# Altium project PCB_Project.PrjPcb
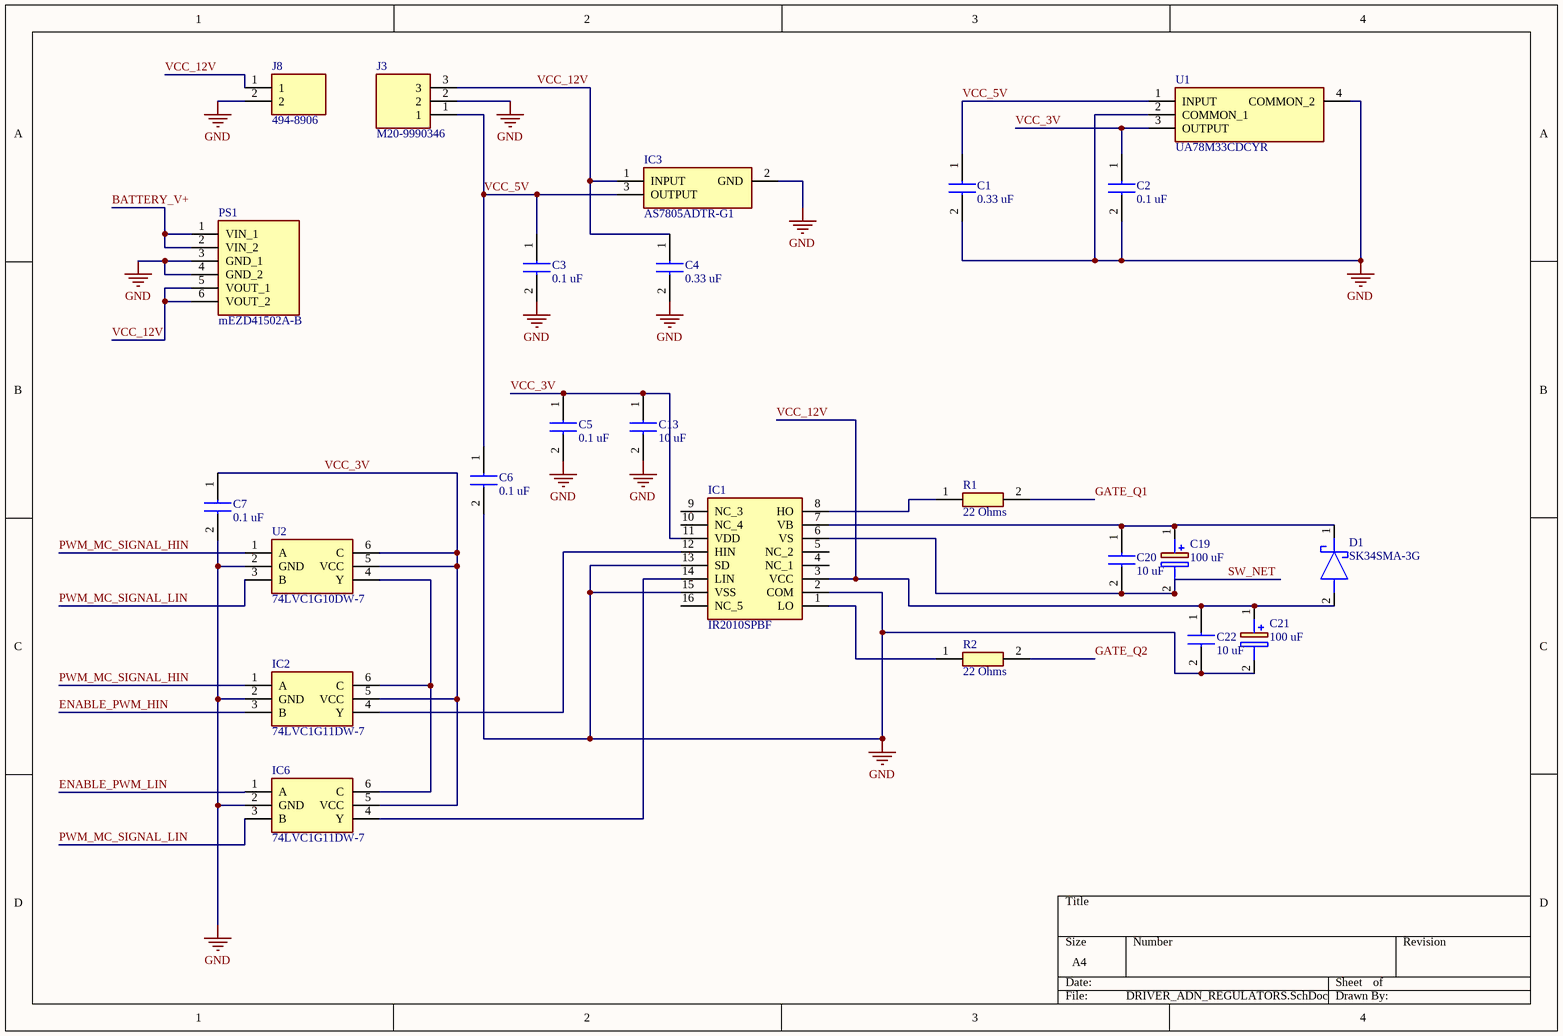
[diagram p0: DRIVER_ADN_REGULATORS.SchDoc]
5 sheets, 99 parts. Net scope: global (net labels, ports and power ports of the same name join across sheets).
Board file: PCB1.PcbDoc
Sheets:
  DRIVER_ADN_REGULATORS.SchDoc
  MOSFET_AND_INTRUMENTAL_AMPLIFIERS.SchDoc
  MCU.SchDoc
  CURRENT_SENSE.SchDoc
  DRIVER_2.SchDoc

## Sheet DRIVER_ADN_REGULATORS.SchDoc
size A4; SheetNumber: 1; SheetTotal: 4

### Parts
C1  0.33 uF  [C0805]
C2  0.1 uF  [C0805]
C3  0.1 uF  [C0805]
C4  0.33 uF  [C0805]
C5  0.1 uF  [C0805]
C6  0.1 uF  [C0805]
C7  0.1 uF  [C0805]
C13  10 uF  [CAPC3216X180N]
C19  100 uF  [CAPPRD250W52D630H1250]
C20  10 uF  [CAPC3216X180N]
C21  100 uF  [CAPPRD250W52D630H1250]
C22  10 uF  [CAPC3216X180N]
D1  SK34SMA-3G  [DIOM5027X240N]
IC1  IR2010SPBF  [SOIC127P1032X265-16N]
IC2  74LVC1G11DW-7  [SOT65P210X110-6N]
IC3  AS7805ADTR-G1  [AS7805ADTRG1]
IC6  74LVC1G11DW-7  [SOT65P210X110-6N]
J3  M20-9990346  [HDRV3W64P0X254_1X3_762X254X864P]
J8  494-8906  [SHDR2W100P0X500_1X2_1000X750X1000P]
PS1  mEZD41502A-B  [mEZD41502AB]
R1  22 Ohms  [RESC6331X75N]
R2  22 Ohms  [RESC6331X75N]
U1  UA78M33CDCYR  [SOT230P700X180-4N]
U2  74LVC1G10DW-7  [SOT65P210X110-6N]

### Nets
GND: C1.2 C2.2 C3.2 C4.2 C5.2 C6.2 C7.2 C13.2 C21.2(-) C22.2 IC1.2(COM) IC1.13(SD) IC1.15(VSS) IC2.2(GND) IC3.2(GND) IC6.2(GND) J3.2 J8.2 PS1.3(GND_1) PS1.4(GND_2) U1.2(COMMON_1) U1.4(COMMON_2) U2.2(GND)
BATTERY_V+: PS1.1(VIN_1) PS1.2(VIN_2)
ENABLE_PWM_HIN: IC2.3(B)
ENABLE_PWM_LIN: IC6.1(A)
GATE_Q1: R1.2
GATE_Q2: R2.2
PWM_MC_SIGNAL_HIN: IC2.1(A) U2.1(A)
PWM_MC_SIGNAL_LIN: IC6.3(B) U2.3(B)
SW_NET: C19.2(-) C20.2 IC1.6(VS)
VCC_3V: C2.1 C5.1 C7.1 C13.1 IC1.11(VDD) IC2.5(VCC) IC6.5(VCC) U1.3(OUTPUT) U2.5(VCC) U2.6(C)
VCC_5V: C1.1 C3.1 C6.1 IC3.3(OUTPUT) J3.1 U1.1(INPUT)
VCC_12V: C4.1 C21.1(+) C22.1 D1.2(A) IC1.3(VCC) IC3.1(INPUT) J3.3 J8.1 PS1.5(VOUT_1) PS1.6(VOUT_2)
NetC19_1: C19.1(+) C20.1 D1.1(K) IC1.7(VB)
NetIC1_1: IC1.1(LO) R2.1
NetIC1_8: IC1.8(HO) R1.1
NetIC1_12: IC1.12(HIN) IC2.4(Y)
NetIC1_14: IC1.14(LIN) IC6.4(Y)
NetIC2_6: IC2.6(C) IC6.6(C) U2.4(Y)

Not connected (* = marked no-connect by the designer): IC1 4(NC_1) 5(NC_2) 9(NC_3) 10(NC_4) 16(NC_5)

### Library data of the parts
C1 C4 = C0805C334K5RACAUTO: Capacitor; Manufacturer_Name: KEMET
C2 C3 C5-C7 = C0805C104M5RACTU: Capacitor; Manufacturer_Name: KEMET
C13 C20 C22 = CL31B106KAHNNNE: Capacitor; Manufacturer_Name: SAMSUNG
C19 C21 = 860010473007: Capacitor Polarised; Manufacturer_Name: Wurth Elektronik
D1 = SK34SMA-3G: Schottky Diode; Manufacturer_Name: Diotec
IC1 = IR2010SPBF: Integrated Circuit; Manufacturer_Name: Infineon
IC2 IC6 = 74LVC1G11DW-7: Integrated Circuit; Manufacturer_Name: Diodes Incorporated
IC3 = AS7805ADTR-G1: Integrated Circuit; Manufacturer_Name: Diodes Incorporated
J3 = M20-9990346: Connector; Manufacturer_Name: Harwin
J8 = 494-8906: Connector; Manufacturer_Name: RS Pro
PS1 = mEZD41502A-B: Power Supply; Manufacturer_Name: Monolithic Power Systems (MPS)
R1 R2 = CR2512-JW-220ELF: Resistor; Manufacturer_Name: Bourns
U1 = UA78M33CDCYR: Undefined or Miscellaneous; Manufacturer_Name: Texas Instruments
U2 = 74LVC1G10DW-7: Undefined or Miscellaneous; Manufacturer_Name: Diodes Incorporated

## Sheet MOSFET_AND_INTRUMENTAL_AMPLIFIERS.SchDoc
size A4; SheetNumber: 2; SheetTotal: 5
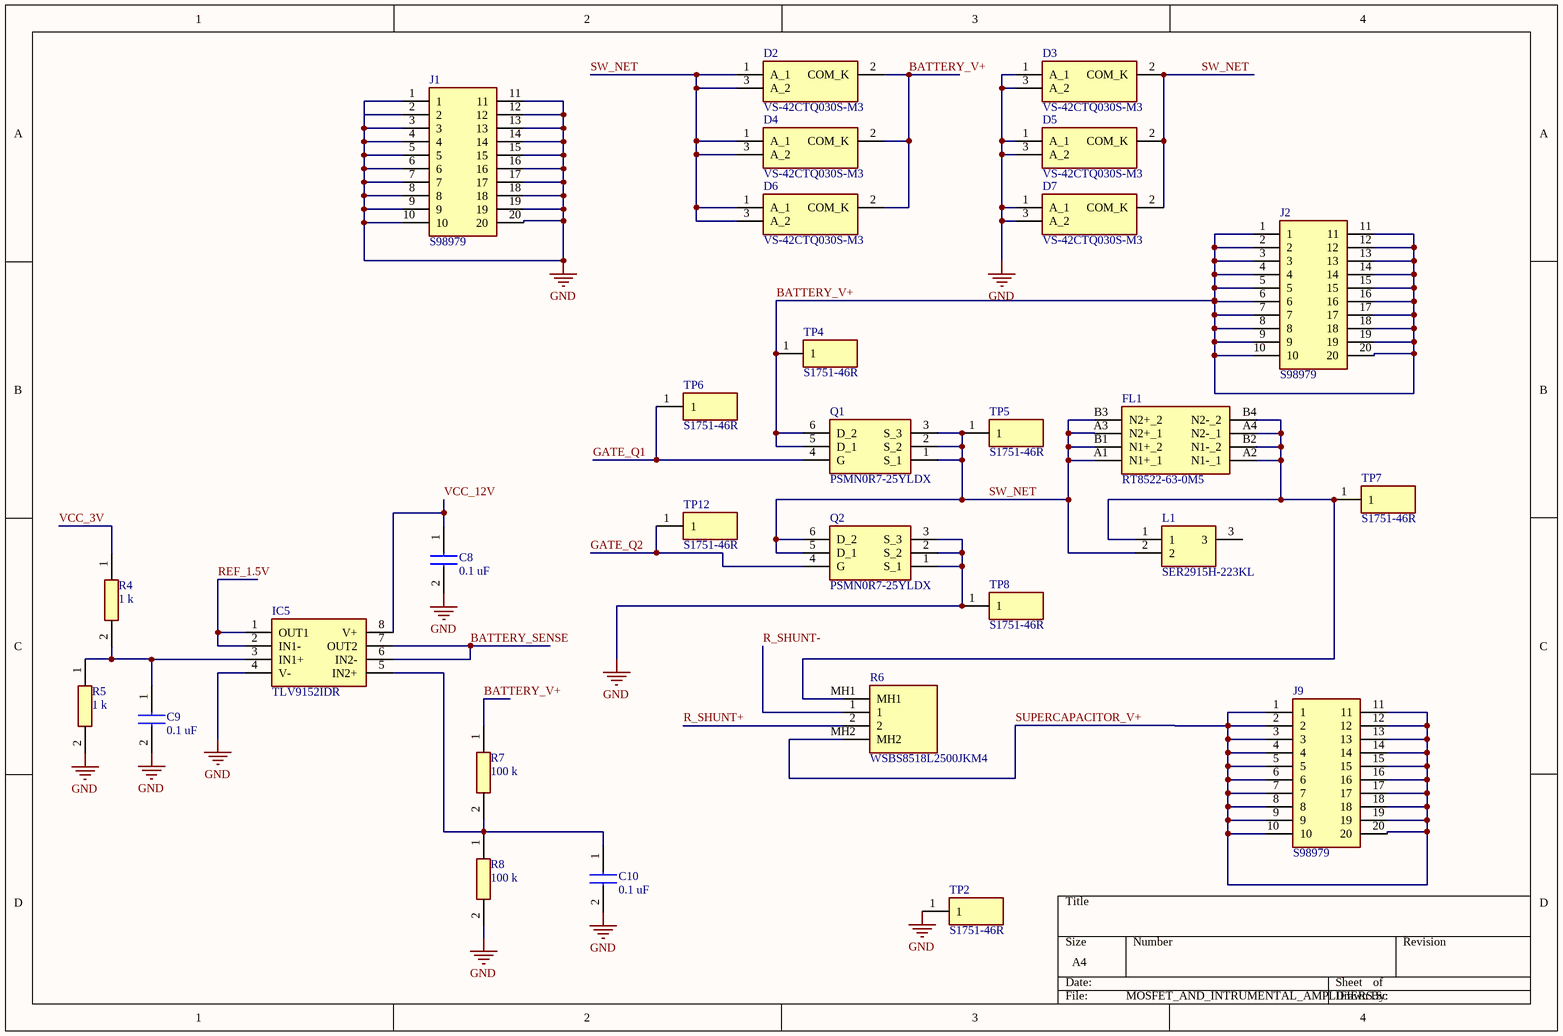
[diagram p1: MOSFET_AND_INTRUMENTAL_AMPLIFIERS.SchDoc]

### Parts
C8  0.1 uF  [C0805]
C9  0.1 uF  [C0805]
C10  0.1 uF  [C0805]
D2  VS-42CTQ030S-M3  [VS42CTQ030SM3]
D3  VS-42CTQ030S-M3  [VS42CTQ030SM3]
D4  VS-42CTQ030S-M3  [VS42CTQ030SM3]
D5  VS-42CTQ030S-M3  [VS42CTQ030SM3]
D6  VS-42CTQ030S-M3  [VS42CTQ030SM3]
D7  VS-42CTQ030S-M3  [VS42CTQ030SM3]
FL1  RT8522-63-0M5  [RT8522630M5]
IC5  TLV9152IDR  [SOIC127P600X175-8N]
J1  S98979  [S98979]
J2  S98979  [S98979]
J9  S98979  [S98979]
L1  SER2915H-223KL  [SER2915H223KL]
Q1  PSMN0R7-25YLDX  [BUK7J1R440HX]
Q2  PSMN0R7-25YLDX  [BUK7J1R440HX]
R4  1 k  [RESC2012X50N]
R5  1 k  [RESC2012X50N]
R6  WSBS8518L2500JKM4  [WSBS8518L2500JKM4]
R7  100 k  [RESC2012X60N]
R8  100 k  [RESC2012X60N]
TP2  S1751-46R  [S175146R]
TP4  S1751-46R  [S175146R]
TP5  S1751-46R  [S175146R]
TP6  S1751-46R  [S175146R]
TP7  S1751-46R  [S175146R]
TP8  S1751-46R  [S175146R]
TP12  S1751-46R  [S175146R]

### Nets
GND: C8.2 C9.2 C10.2 D3.1(A_1) D3.3(A_2) D5.1(A_1) D5.3(A_2) D7.1(A_1) D7.3(A_2) IC5.4(V-) J1.1 J1.2 J1.3 J1.4 J1.5 J1.6 J1.7 J1.8 J1.9 J1.10 J1.11 J1.12 J1.13 J1.14 J1.15 J1.16 J1.17 J1.18 J1.19 J1.20 Q2.1(S_1) Q2.2(S_2) Q2.3(S_3) R5.2 R8.2 TP2.1 TP8.1
BATTERY_SENSE: IC5.6(IN2-) IC5.7(OUT2)
BATTERY_V+: D2.2(COM_K) D4.2(COM_K) D6.2(COM_K) J2.1 J2.2 J2.3 J2.4 J2.5 J2.6 J2.7 J2.8 J2.9 J2.10 J2.11 J2.12 J2.13 J2.14 J2.15 J2.16 J2.17 J2.18 J2.19 J2.20 Q1.5(D_1) Q1.6(D_2) R7.1 TP4.1
GATE_Q1: Q1.4(G) TP6.1
GATE_Q2: Q2.4(G) TP12.1
R_SHUNT+: R6.2
R_SHUNT-: R6.1
REF_1.5V: IC5.1(OUT1) IC5.2(IN1-)
SUPERCAPACITOR_V+: J9.1 J9.2 J9.3 J9.4 J9.5 J9.6 J9.7 J9.8 J9.9 J9.10 J9.11 J9.12 J9.13 J9.14 J9.15 J9.16 J9.17 J9.18 J9.19 J9.20 R6.MH2
SW_NET: D2.1(A_1) D2.3(A_2) D3.2(COM_K) D4.1(A_1) D4.3(A_2) D5.2(COM_K) D6.1(A_1) D6.3(A_2) D7.2(COM_K) FL1.A1(N1+_1) FL1.A3(N2+_1) FL1.B1(N1+_2) FL1.B3(N2+_2) L1.2 Q1.1(S_1) Q1.2(S_2) Q1.3(S_3) Q2.5(D_1) Q2.6(D_2) TP5.1
VCC_3V: R4.1
VCC_12V: C8.1 IC5.8(V+)
NetC9_1: C9.1 IC5.3(IN1+) R4.2 R5.1
NetC10_1: C10.1 IC5.5(IN2+) R7.2 R8.1
NetFL1_A2: FL1.A2(N1-_1) FL1.A4(N2-_1) FL1.B2(N1-_2) FL1.B4(N2-_2) L1.1 R6.MH1 TP7.1

Not connected (* = marked no-connect by the designer): L1 3

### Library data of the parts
C8-C10 = C0805C104M5RACTU: Capacitor; Manufacturer_Name: KEMET
D2-D7 = VS-42CTQ030S-M3: Schottky Diode; Manufacturer_Name: Vishay
FL1 = RT8522-63-0M5: Filter; Manufacturer_Name: Schaffner
IC5 = TLV9152IDR: Integrated Circuit; Manufacturer_Name: Texas Instruments
J1 J2 J9 = S98979: Connector; Manufacturer_Name: Wurth Elektronik
L1 = SER2915H-223KL: Inductor; Manufacturer_Name: COILCRAFT
Q1 Q2 = PSMN0R7-25YLDX: MOSFET (N-Channel); Manufacturer_Name: Nexperia
R4 R5 = CRCW08051K00FKEA: Resistor; Manufacturer_Name: Vishay
R6 = WSBS8518L2500JKM4: Resistor; Manufacturer_Name: Vishay
R7 R8 = CR0805-FX-1003ELF: Resistor; Manufacturer_Name: Bourns
TP2 TP4-TP8 TP12 = S1751-46R: Test Point; Manufacturer_Name: Harwin

## Sheet MCU.SchDoc
size A4; SheetNumber: 3; SheetTotal: 5
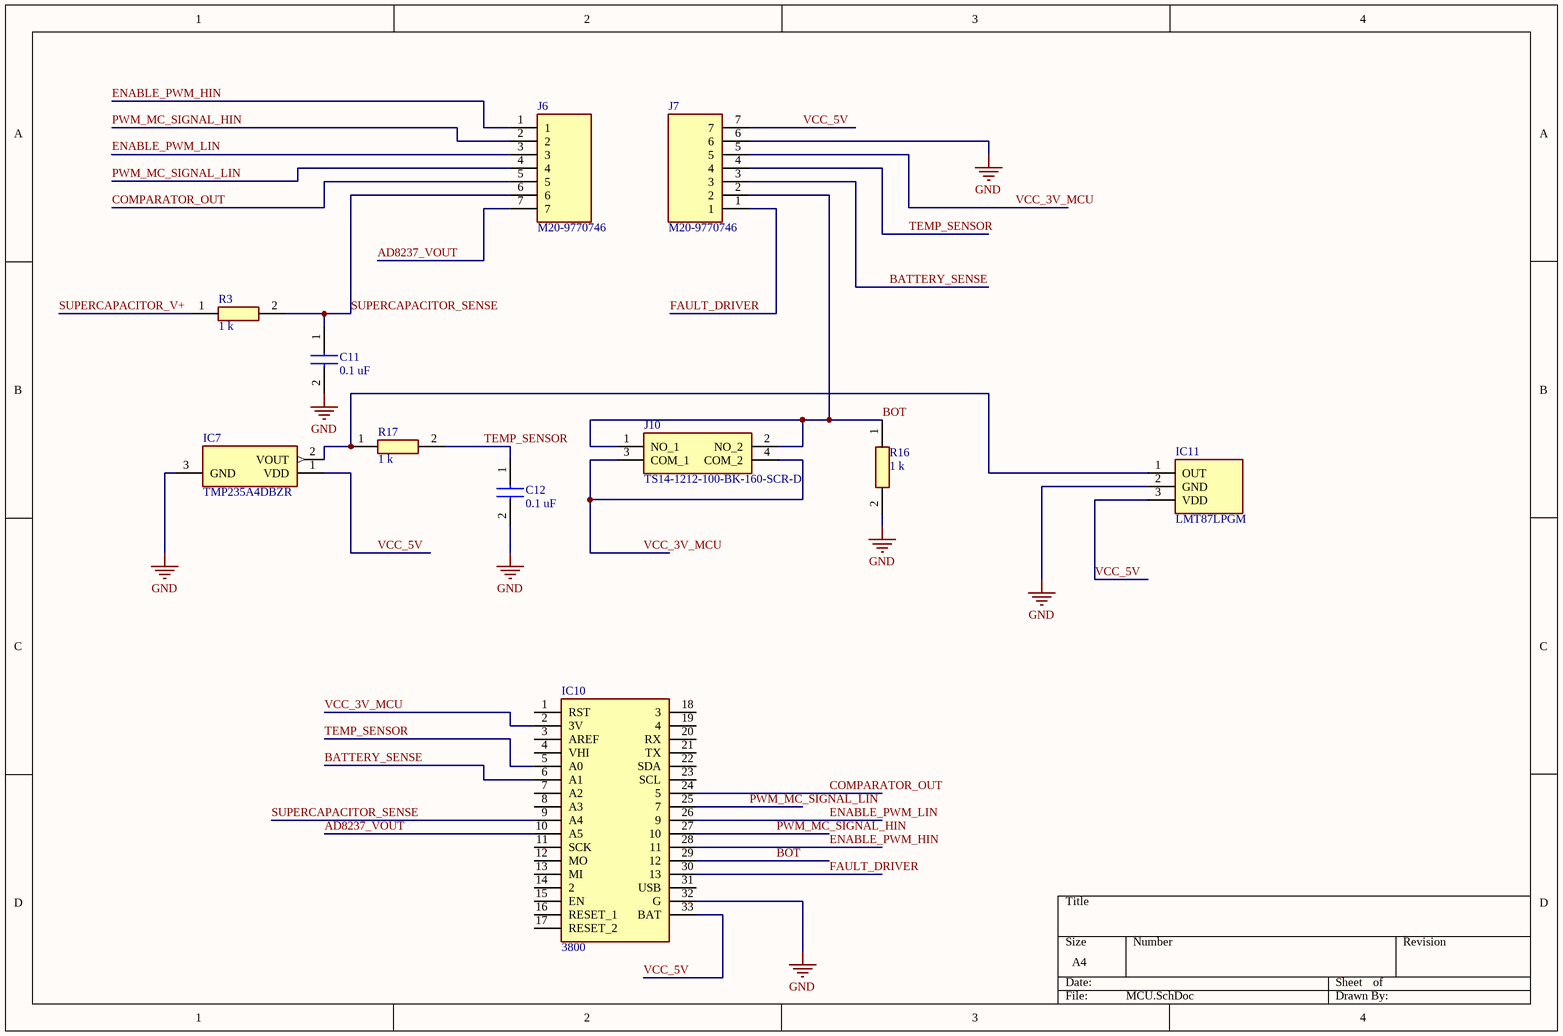
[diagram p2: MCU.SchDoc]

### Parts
C11  0.1 uF  [C0805]
C12  0.1 uF  [C0805]
IC7  TMP235A4DBZR  [SOT95P237X112-3N]
IC10  3800  [3800]
IC11  LMT87LPGM  [TO127P162X315X490-3P]
J6  M20-9770746  [HDRV7W66P0X254_1X7_1778X254X844P]
J7  M20-9770746  [HDRV7W66P0X254_1X7_1778X254X844P]
J10  TS14-1212-100-BK-160-SCR-D  [TS141212100BK160SCRD]
R3  1 k  [RESC2012X50N]
R16  1 k  [RESC2012X50N]
R17  1 k  [RESC2012X50N]

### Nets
GND: C11.2 C12.2 IC7.3(GND) IC10.32(G) IC11.2(GND) J7.6 R16.2
AD8237_VOUT: IC10.10(A5) J6.7
BATTERY_SENSE: IC10.6(A1) J7.3
BOT: IC10.29(12) J7.2 J10.1(NO_1) J10.2(NO_2) R16.1
COMPARATOR_OUT: IC10.24(5) J6.5
ENABLE_PWM_HIN: IC10.28(11) J6.1
ENABLE_PWM_LIN: IC10.26(9) J6.3
FAULT_DRIVER: IC10.30(13) J7.1
PWM_MC_SIGNAL_HIN: IC10.27(10) J6.2
PWM_MC_SIGNAL_LIN: IC10.25(7) J6.4
SUPERCAPACITOR_SENSE: C11.1 IC10.9(A4) J6.6 R3.2
SUPERCAPACITOR_V+: R3.1
TEMP_SENSOR: C12.1 IC10.5(A0) J7.4 R17.2
VCC_3V_MCU: IC10.2(3V) J7.5 J10.3(COM_1) J10.4(COM_2)
VCC_5V: IC7.1(VDD) IC10.33(BAT) IC11.3(VDD) J7.7
NetIC7_2: IC7.2(VOUT) IC11.1(OUT) R17.1

Not connected (* = marked no-connect by the designer): IC10 1(RST) 3(AREF) 4(VHI) 7(A2) 8(A3) 11(SCK) 12(MO) 13(MI) 14(2) 15(EN) 16(RESET_1) 17(RESET_2) 18(3) 19(4) 20(RX) 21(TX) 22(SDA) 23(SCL) 31(USB)

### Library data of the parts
C11 C12 = C0805C104M5RACTU: Capacitor; Manufacturer_Name: KEMET
IC7 = TMP235A4DBZR: Integrated Circuit; Manufacturer_Name: Texas Instruments
IC10 = 3800: Integrated Circuit; Manufacturer_Name: Adafruit
IC11 = LMT87LPGM: Integrated Circuit; Manufacturer_Name: Texas Instruments
J6 J7 = M20-9770746: Connector; Manufacturer_Name: Harwin
J10 = TS14-1212-100-BK-160-SCR-D: Connector; Manufacturer_Name: Same Sky
R3 R16 R17 = CRCW08051K00FKEA: Resistor; Manufacturer_Name: Vishay

## Sheet CURRENT_SENSE.SchDoc
size A4; SheetNumber: 4; SheetTotal: 4
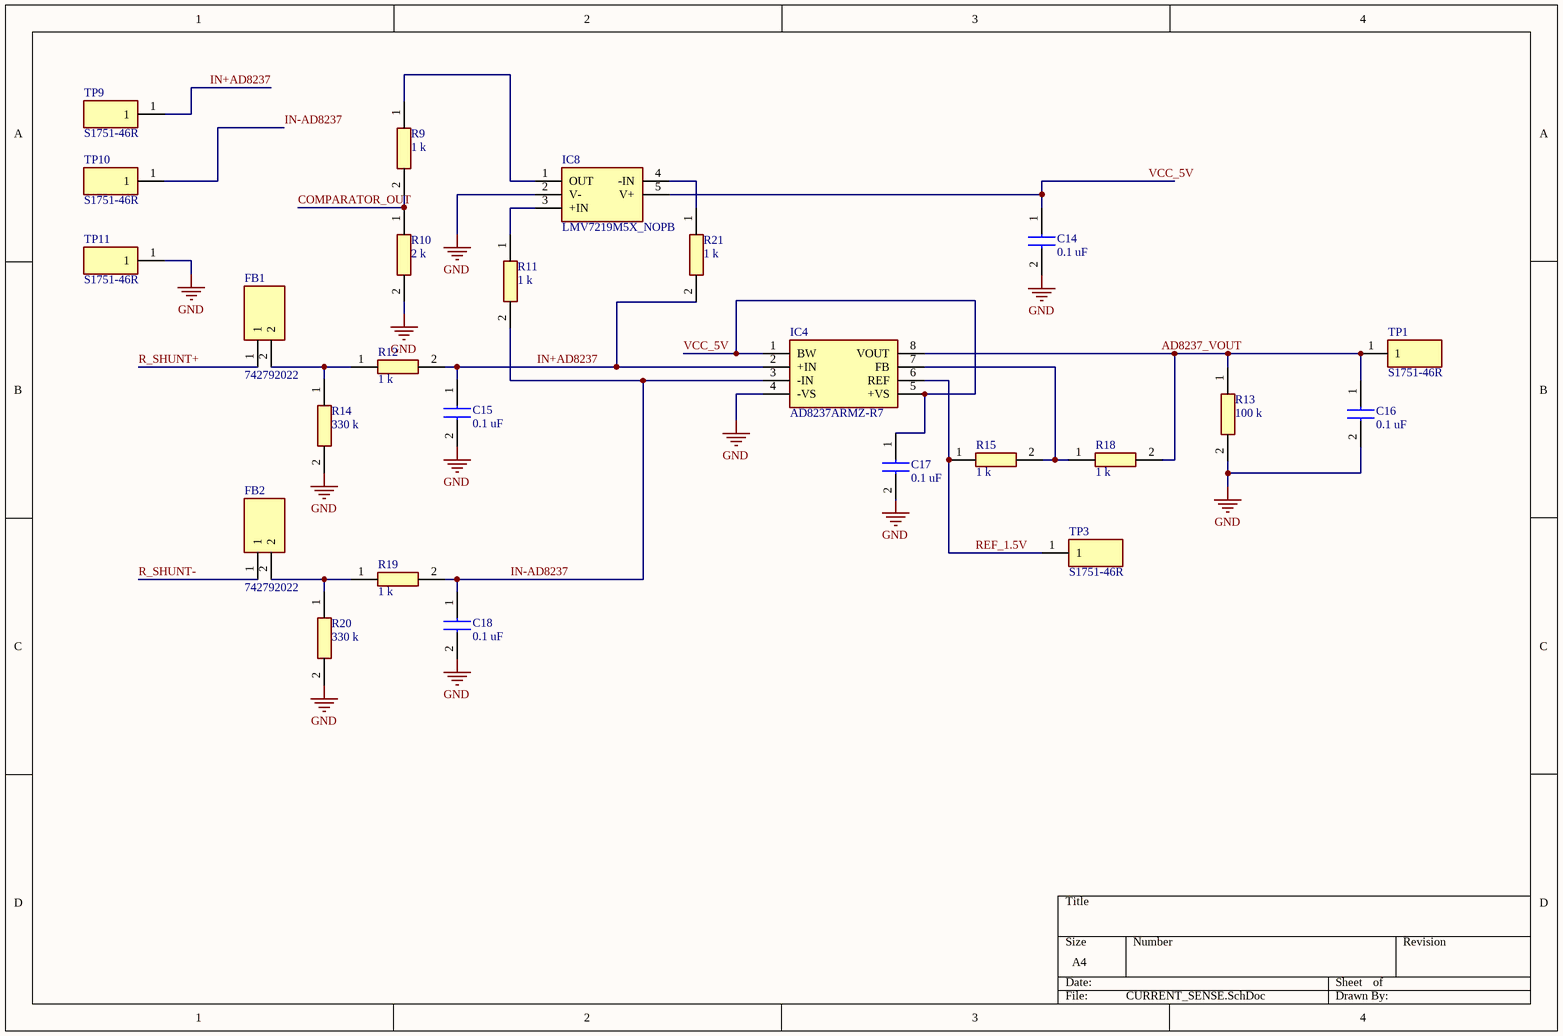
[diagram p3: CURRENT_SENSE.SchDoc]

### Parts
C14  0.1 uF  [C0805]
C15  0.1 uF  [C0805]
C16  0.1 uF  [C0805]
C17  0.1 uF  [C0805]
C18  0.1 uF  [C0805]
FB1  742792022  [BEADC2012X110N]
FB2  742792022  [BEADC2012X110N]
IC4  AD8237ARMZ-R7  [SOP65P490X110-8N]
IC8  LMV7219M5X_NOPB  [SOT95P280X145-5N]
R9  1 k  [RESC2012X50N]
R10  2 k  [RESC2012X60N]
R11  1 k  [RESC2012X50N]
R12  1 k  [RESC2012X50N]
R13  100 k  [RESC2012X60N]
R14  330 k  [RESC2012X70N]
R15  1 k  [RESC2012X50N]
R18  1 k  [RESC2012X50N]
R19  1 k  [RESC2012X50N]
R20  330 k  [RESC2012X70N]
R21  1 k  [RESC2012X50N]
TP1  S1751-46R  [S175146R]
TP3  S1751-46R  [S175146R]
TP9  S1751-46R  [S175146R]
TP10  S1751-46R  [S175146R]
TP11  S1751-46R  [S175146R]

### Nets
GND: C14.2 C15.2 C16.2 C17.2 C18.2 IC4.4(-VS) IC8.2(V-) R10.2 R13.2 R14.2 R20.2 TP11.1
AD8237_VOUT: C16.1 IC4.8(VOUT) R13.1 R18.2 TP1.1
COMPARATOR_OUT: R9.2 R10.1
IN+AD8237: C15.1 IC4.2(+IN) R12.2 R21.2 TP9.1
IN-AD8237: C18.1 IC4.3(-IN) R11.2 R19.2 TP10.1
R_SHUNT+: FB1.1
R_SHUNT-: FB2.1
REF_1.5V: IC4.6(REF) R15.1 TP3.1
VCC_5V: C14.1 C17.1 IC4.1(BW) IC4.5(+VS) IC8.5(V+)
NetFB1_2: FB1.2 R12.1 R14.1
NetFB2_2: FB2.2 R19.1 R20.1
NetIC4_7: IC4.7(FB) R15.2 R18.1
NetIC8_1: IC8.1(OUT) R9.1
NetIC8_3: IC8.3(+IN) R11.1
NetIC8_4: IC8.4(-IN) R21.1

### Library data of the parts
C14-C18 = C0805C104M5RACTU: Capacitor; Manufacturer_Name: KEMET
FB1 FB2 = 742792022: Ferrite Bead; Manufacturer_Name: Wurth Elektronik
IC4 = AD8237ARMZ-R7: Integrated Circuit; Manufacturer_Name: Analog Devices
IC8 = LMV7219M5X_NOPB: Integrated Circuit; Manufacturer_Name: Texas Instruments; Manufacturer_Part_Number: LMV7219M5X/NOPB
R9 R11 R12 R15 R18 R19 R21 = CRCW08051K00FKEA: Resistor; Manufacturer_Name: Vishay
R10 = CR0805-JW-202ELF: Resistor; Manufacturer_Name: Bourns
R13 = CR0805-FX-1003ELF: Resistor; Manufacturer_Name: Bourns
R14 R20 = ERJ-6GEYJ334V: Resistor; Manufacturer_Name: Panasonic
TP1 TP3 TP9-TP11 = S1751-46R: Test Point; Manufacturer_Name: Harwin

## Sheet DRIVER_2.SchDoc
size A4; SheetNumber: 5; SheetTotal: 5
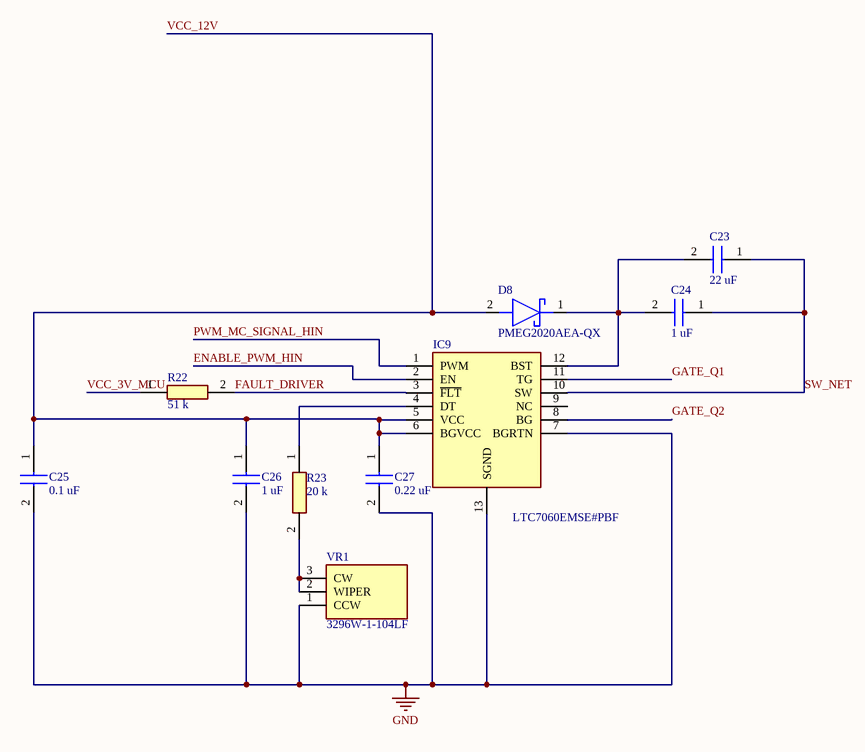
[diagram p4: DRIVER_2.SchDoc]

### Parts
C23  22 uF  [CAPC3225X270N]
C24  1 uF  [CAPC2012X135N]
C25  0.1 uF  [CAPC2012X88N]
C26  1 uF  [CAPC2012X135N]
C27  0.22 uF  [CAPC2012X140N]
D8  PMEG2020AEA-QX  [SOD2512X110N]
IC9  LTC7060EMSE#PBF  [SOP65P490X110-13N]
R22  51 k  [RESC2013X65N]
R23  20 k  [RESC2012X60N]
VR1  3296W-1-104LF  [3296W1503LF]

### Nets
GND: C25.2 C26.2 C27.2 IC9.7(BGRTN) IC9.13(SGND) VR1.1(CCW)
ENABLE_PWM_HIN: IC9.2(EN)
FAULT_DRIVER: IC9.3(~{FLT}) R22.2
GATE_Q1: IC9.11(TG)
GATE_Q2: IC9.8(BG)
PWM_MC_SIGNAL_HIN: IC9.1(PWM)
SW_NET: C23.1 C24.1 IC9.10(SW)
VCC_3V_MCU: R22.1
VCC_12V: C25.1 C26.1 C27.1 D8.2(A) IC9.5(VCC) IC9.6(BGVCC)
NetC23_2: C23.2 C24.2 D8.1(K) IC9.12(BST)
NetIC9_4: IC9.4(DT) R23.1
NetR23_2: R23.2 VR1.2(WIPER) VR1.3(CW)

Not connected (* = marked no-connect by the designer): IC9 9(NC)

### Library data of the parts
C23 = CL32B226KAJNNNE: Capacitor; Manufacturer_Name: SAMSUNG
C24 C26 = CL21B105MBFNNNE: Capacitor; Manufacturer_Name: SAMSUNG
C25 = C0805C104M5RAC: Capacitor; Manufacturer_Name: KEMET
C27 = C0805C224K5RAC7800: Capacitor; Manufacturer_Name: KEMET
D8 = PMEG2020AEA-QX: Schottky Diode; Manufacturer_Name: Nexperia
IC9 = LTC7060EMSE#PBF: Integrated Circuit; Manufacturer_Name: Analog Devices
R22 = 0805W8F5102T5E: Resistor; Manufacturer_Name: UNI-ROYAL(Uniroyal Elec)
R23 = CR0805-FX-2002ELF: Resistor; Manufacturer_Name: Bourns
VR1 = 3296W-1-104LF: Variable Resistor; Manufacturer_Name: Bourns

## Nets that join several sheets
GND: DRIVER_ADN_REGULATORS (23 pins), MOSFET_AND_INTRUMENTAL_AMPLIFIERS (37 pins), MCU (7 pins), CURRENT_SENSE (12 pins), DRIVER_2 (6 pins)
AD8237_VOUT: MCU (IC10.10 J6.7), CURRENT_SENSE (5 pins)
BATTERY_SENSE: MOSFET_AND_INTRUMENTAL_AMPLIFIERS (IC5.6 IC5.7), MCU (IC10.6 J7.3)
BATTERY_V+: DRIVER_ADN_REGULATORS (PS1.1 PS1.2), MOSFET_AND_INTRUMENTAL_AMPLIFIERS (27 pins)
COMPARATOR_OUT: MCU (IC10.24 J6.5), CURRENT_SENSE (R9.2 R10.1)
ENABLE_PWM_HIN: DRIVER_ADN_REGULATORS (IC2.3), MCU (IC10.28 J6.1), DRIVER_2 (IC9.2)
ENABLE_PWM_LIN: DRIVER_ADN_REGULATORS (IC6.1), MCU (IC10.26 J6.3)
FAULT_DRIVER: MCU (IC10.30 J7.1), DRIVER_2 (IC9.3 R22.2)
GATE_Q1: DRIVER_ADN_REGULATORS (R1.2), MOSFET_AND_INTRUMENTAL_AMPLIFIERS (Q1.4 TP6.1), DRIVER_2 (IC9.11)
GATE_Q2: DRIVER_ADN_REGULATORS (R2.2), MOSFET_AND_INTRUMENTAL_AMPLIFIERS (Q2.4 TP12.1), DRIVER_2 (IC9.8)
PWM_MC_SIGNAL_HIN: DRIVER_ADN_REGULATORS (IC2.1 U2.1), MCU (IC10.27 J6.2), DRIVER_2 (IC9.1)
PWM_MC_SIGNAL_LIN: DRIVER_ADN_REGULATORS (IC6.3 U2.3), MCU (IC10.25 J6.4)
R_SHUNT+: MOSFET_AND_INTRUMENTAL_AMPLIFIERS (R6.2), CURRENT_SENSE (FB1.1)
R_SHUNT-: MOSFET_AND_INTRUMENTAL_AMPLIFIERS (R6.1), CURRENT_SENSE (FB2.1)
REF_1.5V: MOSFET_AND_INTRUMENTAL_AMPLIFIERS (IC5.1 IC5.2), CURRENT_SENSE (IC4.6 R15.1 TP3.1)
SUPERCAPACITOR_V+: MOSFET_AND_INTRUMENTAL_AMPLIFIERS (21 pins), MCU (R3.1)
SW_NET: DRIVER_ADN_REGULATORS (C19.2 C20.2 IC1.6), MOSFET_AND_INTRUMENTAL_AMPLIFIERS (20 pins), DRIVER_2 (C23.1 C24.1 IC9.10)
VCC_3V: DRIVER_ADN_REGULATORS (10 pins), MOSFET_AND_INTRUMENTAL_AMPLIFIERS (R4.1)
VCC_3V_MCU: MCU (IC10.2 J7.5 J10.3 J10.4), DRIVER_2 (R22.1)
VCC_5V: DRIVER_ADN_REGULATORS (6 pins), MCU (IC7.1 IC10.33 IC11.3 J7.7), CURRENT_SENSE (5 pins)
VCC_12V: DRIVER_ADN_REGULATORS (10 pins), MOSFET_AND_INTRUMENTAL_AMPLIFIERS (C8.1 IC5.8), DRIVER_2 (6 pins)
